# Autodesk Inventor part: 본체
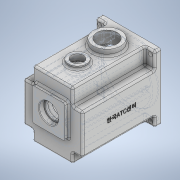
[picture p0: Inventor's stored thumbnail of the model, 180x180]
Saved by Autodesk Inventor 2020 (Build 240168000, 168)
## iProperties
Created: 2022-01
Part Number: 본체
Material: 일반
Document SubType Name: Modeling
Designer: user
Density: 1 g/cm^3
Appearance: 기본값
Mass: 519.685 g
Surface Area: 1174.34 cm^2
Volume: 519.685 cm^3
Author: user
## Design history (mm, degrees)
sketch "스케치1"
  geometry: 1 further point
sketch "스케치2"
  geometry: L1 (-49, 55)-(49, 55); L2 (49, 55)-(49, -55); L3 (49, -55)-(-49, -55); L4 (-49, -55)-(-49, 55); L5 (-49, 55)-(49, -55); L6 (49, 55)-(-49, -55); 1 further point
  constraints: 12 end point, 2 midpoint, 2 parallel, 1 horizontal, 1 perpendicular
  dimensions: "d0" = 98 distance of L2.end L3.end; "d1" = 110 distance of L1.end L2.end
extrude "돌출1" new body sketch "스케치2" distance "d2" = 10; taper "d3" = 0 deg
sketch "스케치3"
  geometry: L1 (49, -55)-(49, 55) reference; L2 (49, 55)-(-49, 55) reference; L3 (-49, 55)-(-49, -55) reference; L4 (-49, -55)-(49, -55) reference; L5 (49, -55)-(49, 55) reference; L6 (49, 55)-(33, 55); L7 (33, 55)-(33, 28); L8 (33, 28)-(49, 28); L9 (49, 28)-(49, 55); L10 (49, -55)-(33, -55); L11 (33, -55)-(33, -38); L12 (33, -38)-(49, -38); L13 (49, -38)-(49, -55); L14 (-49, -55)-(49, -55) reference; L15 (-49, -55)-(-33, -55); L16 (-33, -55)-(-33, -38); L17 (-33, -38)-(-49, -38); L18 (-49, -38)-(-49, -55); L19 (-49, 55)-(-49, -55) reference; L20 (-49, 55)-(-33, 55); L21 (-33, 55)-(-33, 28); L22 (-33, 28)-(-49, 28); L23 (-49, 28)-(-49, 55); 9 further points
  constraints: 32 end point, 8 parallel, 4 horizontal, 4 perpendicular, 1 point on line
  dimensions: "d4" = 27 distance of L6.end L7.end; "d5" = 16 distance of L7.end L8.end; "d6" = 17 distance of L10.end L11.end; "d7" = 16 distance of L11.end L12.end; "d8" = 27 distance of L20.end L21.end; "d9" = 16 distance of L21.end L22.end; "d10" = 16 distance of L16.end L17.end
extrude "돌출2" join sketch "스케치3" distance "d11" = 120; taper "d12" = 0 deg
sketch "스케치4"
  geometry: 1 further point
sketch "스케치5"
  geometry: L1 (49, -55)-(-49, -55) reference; L2 (-26, 48)-(26, 48); L3 (26, 48)-(26, 27.588); L4 (26, 27.588)-(-26, 27.588); L5 (-26, 27.588)-(-26, 48); C1 r 45 at (0, -5); 3 further points
  constraints: 8 end point, 2 parallel, 1 centre point, 1 horizontal, 1 perpendicular, 1 vertical alignment
  dimensions: "d13" = 90 diameter of C1; "d14" = 50 distance from line of L1 C1.centre; "d15" = 53 distance from line of L2 C1.centre; "d16" = 52 distance of L2.start L2.end; "d17" = 26 horizontal distance of C1.centre L2.start
extrude "돌출3" cut sketch "스케치5" distance "d18" = 9; taper "d19" = 0 deg
sketch "스케치6" dims "d27" = 8, "d28" = 8
  geometry: L1 (-26, 31.729)-(-26, 48) reference; L2 (26, 48)-(26, 31.729) reference; L3 (-26, 48)-(26, 48) reference; L4 (-23, 45)-(23, 45); L5 (23, 45)-(23, 21.058); L6 (23, 21.058)-(-23, 21.058); L7 (-23, 21.058)-(-23, 45); L8 (-35.778, -1.006)-(-41.81, -1.006); L9 (-35.778, -8.994)-(-41.81, -8.994); L10 (35.778, -1.006)-(42, -1.006); L11 (35.778, -8.994)-(41.81, -8.994); A1 r 45 centre (0, -5) between (-26, 31.729) and (26, 31.729) reference; A2 r 36 centre (0, -5) between (36, -5) and (-36, -5); A3 r 42 centre (0, -5) between (-41.81, -8.994) and (41.81, -8.994); A4 r 42 centre (0, -5) between (41.81, -1.006) and (-41.81, -1.006); 7 further points
  constraints: 16 end point, 10 point on circle, 4 horizontal, 3 centre point, 2 coincident, 2 horizontal alignment, 2 parallel, 1 perpendicular, 1 point on line, 6 other
  dimensions: "d21" = 46 distance of L4.start L4.end; "d22" = 23 distance from line of A1.centre L7; "d23" = 50 distance from line of A1.centre L4; "d26" = 72 diameter of A2
  node "투영된 루프2"
extrude "돌출4" cut sketch "스케치6" distance "d29" = 112; taper "d30" = 0 deg
fillet "모깎기1" dims "d31" = 3
sketch "스케치8"
  geometry: L1 (98, 0)-(0, 0) reference; C1 r 22.5 at (49, -40); C2 r 15 at (49, -89); 2 further points
  constraints: 2 centre point, 2 vertical alignment, 1 midpoint
  dimensions: "d32" = 45 diameter of C1; "d33" = 30 diameter of C2; "d34" = 40 distance of C1.centre point (49, 0); "d35" = 49 distance of C1.centre C2.centre
extrude "돌출5" join sketch "스케치8" distance "d36" = 10; taper "d37" = 0 deg
sketch "스케치9"
  geometry: C1 r 22.5 at (49, -40) reference; C2 r 15 at (49, -89); 1 further point
  constraints: 1 centre point, 1 vertical alignment
  dimensions: "d38" = 30 diameter of C2; "d39" = 49 distance of C1.centre C2.centre
extrude "돌출6" join sketch "스케치9" distance "d40" = 5; taper "d41" = 0 deg
sketch "스케치10"
  geometry: 1 further point
sketch "스케치11"
  geometry: C1 r 21 at (0, 6); C2 r 15 at (0, -25); C3 r 42 at (0, -5); A1 r 42 centre (0, -5) between (-23, 30.143) and (-41.319, 2.532) reference; 3 further points
  constraints: 3 centre point, 2 vertical alignment, 1 coincident
  dimensions: "d42" = 42 diameter of C1; "d43" = 30 diameter of C2; "d44" = 20 distance of C2.centre C3.centre; "d45" = 11 distance of C1.centre C3.centre
sketch "스케치12"
  geometry: C1 r 22.5 at (0, 0) reference; 2 further points
  constraints: 1 coincident
hole "구멍1" sketch "스케치12" at (0, 0) diameter "d46" = 33.376; stored, may be unused: countersink angle "d50" = 90 deg, drill point angle "d52" = 118 deg; dims "d47" = 70, "d48" = 4, "d49" = 2, "d51" = 77.3
extrude "돌출7" join sketch "스케치11" distance "d53" = 7; taper "d54" = 0 deg
sketch "스케치13"
  geometry: C1 r 11 at (0, -25); A1 r 15 centre (0, -25) between (-8.978, -12.984) and (8.978, -12.984) reference; 1 further point
  constraints: 1 centre point, 1 coincident
  dimensions: "d55" = 22 diameter of C1
extrude "돌출8" cut sketch "스케치13" distance "d56" = 7; taper "d57" = 0 deg
sketch "스케치14"
  geometry: C1 r 17.5 at (0, 6); A1 r 21 centre (0, 6) between (8.978, -12.984) and (-8.978, -12.984) reference; 1 further point
  constraints: 1 centre point, 1 coincident
  dimensions: "d58" = 35 diameter of C1
extrude "돌출9" cut sketch "스케치14" distance "d59" = 10; taper "d60" = 0 deg
sketch "스케치15"
  geometry: C1 r 11 at (0, 0) reference; C2 r 9.5 at (0, 0); 1 further point
  constraints: 1 centre point, 1 coincident
  dimensions: "d61" = 19 diameter of C2
extrude "돌출10" cut sketch "스케치15" distance "d62" = 3; taper "d63" = 0 deg
sketch "스케치16"
  geometry: C1 r 17.5 at (0, 0) reference; C2 r 14 at (0, 0); 1 further point
  constraints: 1 centre point, 1 coincident
  dimensions: "d64" = 28 diameter of C2
sketch "스케치17"
  geometry: 1 further point
sketch "스케치18"
  geometry: 1 further point
sketch "스케치19"
  geometry: L1 (-27, 33)-(27, 33); L2 (27, 33)-(27, -21); L3 (27, -21)-(-27, -21); L4 (-27, -21)-(-27, 33); L5 (-27, 33)-(27, -21); L6 (27, 33)-(-27, -21); 4 further points
  constraints: 12 end point, 3 midpoint, 2 parallel, 1 coincident, 1 horizontal, 1 perpendicular
  dimensions: "d65" = 54 distance of L2.end L3.end; "d66" = 54 distance of L1.end L2.end
extrude "돌출11" join sketch "스케치19" distance "d67" = 7; taper "d68" = 0 deg
sketch "스케치20"
  geometry: C1 r 16 at (0, 6); A1 r 21 centre (0, 6) between (8.978, -12.984) and (-8.978, -12.984) reference; 1 further point
  constraints: 1 centre point, 1 coincident
  dimensions: "d69" = 32 diameter of C1
extrude "돌출12" cut sketch "스케치20" distance "d70" = 8.3; taper "d71" = 0 deg
sketch "스케치21"
  geometry: C1 r 16 at (0, 0) reference; C2 r 14 at (0, 0); 1 further point
  constraints: 1 centre point, 1 coincident
  dimensions: "d72" = 28 diameter of C2
extrude "돌출13" cut sketch "스케치21" distance "d73" = 8.3; taper "d74" = 0 deg
sketch "스케치22"
  geometry: 1 further point
sketch "스케치23"
  geometry: C1 r 15 at (23, 80) reference; C2 r 15 at (23, 80); 1 further point
  constraints: 1 centre point, 1 coincident
  dimensions: "d75" = 30 diameter of C2
extrude "돌출14" cut sketch "스케치23" distance "d76" = 5; taper "d77" = 0 deg
sketch "스케치24"
  geometry: C1 r 15 at (0, 0) reference; C2 r 10 at (0, 0); 1 further point
  constraints: 1 centre point, 1 coincident
  dimensions: "d78" = 20 diameter of C2
extrude "돌출15" cut sketch "스케치24" stored distance "d79" = 5; taper "d80" = 0 deg
sketch "스케치25"
  geometry: L1 (33, -55)-(49, -55) reference; L2 (49, -55)-(49, -38) reference; L3 (-49, -38)-(-49, -55) reference; L4 (-49, -55)-(-33, -55) reference; L5 (-33, 55)-(-49, 55) reference; L6 (-49, 55)-(-49, 28) reference; L7 (49, 55)-(33, 55) reference; L8 (49, 28)-(49, 55) reference; C1 r 3.5 at (42, -48); C2 r 3.5 at (-42, -48); C3 r 3.5 at (-42, 48); C4 r 3.5 at (42, 48); 1 further point
  constraints: 4 centre point
  dimensions: "d81" = 7 diameter of C1; "d82" = 7 diameter of C2; "d83" = 7 diameter of C3; "d84" = 7 diameter of C4; "d85" = 7 distance from line of L1 C1.centre; "d86" = 7 distance from line of L2 C1.centre; "d87" = 7 distance from line of L3 C2.centre; "d88" = 7 distance from line of L4 C2.centre; "d89" = 7 distance from line of L5 C3.centre; "d90" = 7 distance from line of L6 C3.centre; "d91" = 7 distance from line of L7 C4.centre; "d92" = 7 distance from line of L8 C4.centre
extrude "돌출16" cut sketch "스케치25" distance "d93" = 10; taper "d94" = 0 deg
sketch "스케치26"
  geometry: A1 r 4 centre (-36, -5) between (-36.222, -8.994) and (-36.222, -1.006) reference; A2 r 4 centre (36, -5) between (36.222, -1.006) and (36.222, -8.994) reference; 3 further points
  constraints: 2 coincident
hole "구멍2" sketch "스케치26" at (-36, -5), (36, -5) diameter "d95" = 3.242; stored, may be unused: countersink angle "d99" = 90 deg, drill point angle "d101" = 118 deg; dims "d96" = 7, "d97" = 4, "d98" = 2, "d100" = 9
fillet "모깎기2" dims "d102" = 6
fillet "모깎기3" dims "d103" = 6
fillet "모깎기4" dims "d104" = 3
chamfer "모따기1" distance "d105" = 1; stored, may be unused: second distance "d106" = 2, angle "d107" = 45 deg
fillet "모깎기5" dims "d108" = 3
fillet "모깎기6" dims "d109" = 0.3
chamfer "모따기2" distance "d110" = 1; stored, may be unused: second distance "d111" = 2, angle "d112" = 45 deg
fillet "모깎기7" dims "d113" = 0.3
chamfer "모따기3" distance "d114" = 1; stored, may be unused: second distance "d115" = 2, angle "d116" = 45 deg
fillet "모깎기8" dims "d117" = 3
fillet "모깎기9" dims "d118" = 3
fillet "모깎기10" dims "d119" = 3
fillet "모깎기11" dims "d120" = 3
fillet "모깎기12" dims "d121" = 3
fillet "모깎기13" dims "d122" = 3
sketch "스케치27"
  geometry: 1 further point
fillet "모깎기14" dims "d123" = 3
sketch "스케치28"
  geometry: 1 further point
sketch "스케치29"
  geometry: L1 (-3, 60)-(-3, 0) reference; L2 (114, 90)-(0, 90) reference; 2 further points
  constraints: 1 other
  dimensions: "d124" = 65 distance from line of L1 point (62, 30); "d125" = 60 distance from line of L2 point (62, 30)
feature "엠보싱1" sketch "스케치29" dims "d4" = 27, "d5" = 16, "d126" = 0.5, "d127" = 0
fillet "모깎기15" dims "d128" = 3
fillet "모깎기16" dims "d129" = 3
chamfer "모따기4" distance "d131" = 1; stored, may be unused: second distance "d132" = 2, angle "d133" = 45 deg
node "솔리드1"
node "투영된 루프1"
node "투영된 루프3"
feature "A9D066F2-1C7D-4E18-AEED-F7BC21143FA4" dims "d46" = 33.376, "d47" = 70, "d48" = 4, "d49" = 2, "d50" = 90 deg, "d51" = 77.3, "d52" = 118 deg
other parameters: "d20" = 84
